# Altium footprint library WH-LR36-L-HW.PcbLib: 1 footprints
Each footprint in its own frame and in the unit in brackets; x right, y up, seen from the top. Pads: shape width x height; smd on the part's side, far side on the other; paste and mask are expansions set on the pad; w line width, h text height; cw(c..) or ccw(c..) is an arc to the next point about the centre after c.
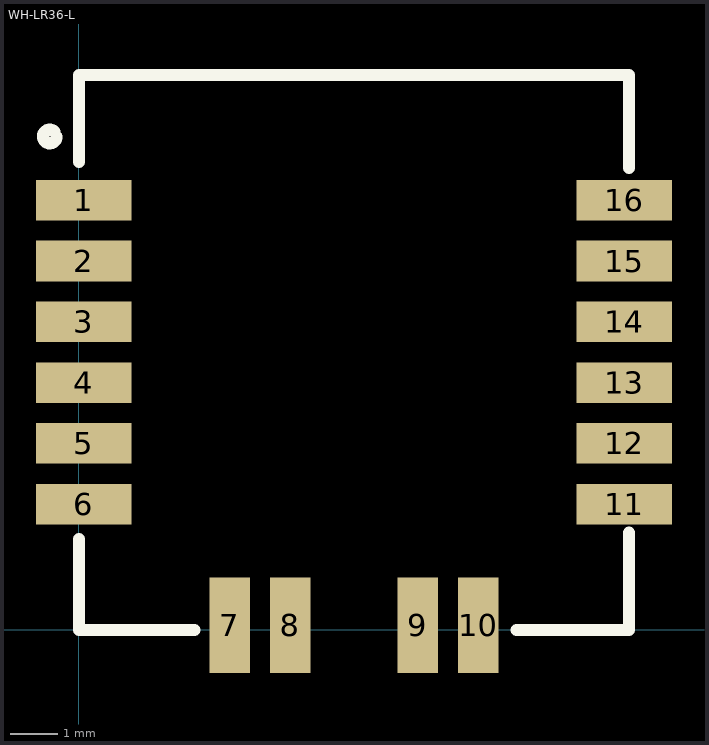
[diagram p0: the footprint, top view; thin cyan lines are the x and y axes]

## WH-LR36-L [mm] "WH-LR36-L封装"
height 2.13
pads (16):
  rect 2x0.85 smd: 1(0.1,8.98) 2(0.1,7.71) 3(0.1,6.44) 4(0.1,5.17) 5(0.1,3.9) 6(0.1,2.63) 11(11.4,2.63) 12(11.4,3.9) 13(11.4,5.17) 14(11.4,6.44) 15(11.4,7.71) 16(11.4,8.98)
  rect 0.85x2 smd: 7(3.15,0.1) 8(4.42,0.1) 9(7.08,0.1) 10(8.35,0.1)
Top Overlay:
  lines w0.254: -0.508,10.414 ccw(c-0.608,10.314) -0.467,10.314 ; 0,1.905 0,0 2.413,0 ; 0,9.779 0,11.557 ; 0,11.6 11.5,11.6 ; 9.144,0 11.5,0 11.5,2.032 ; 11.5,9.652 11.5,11.557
